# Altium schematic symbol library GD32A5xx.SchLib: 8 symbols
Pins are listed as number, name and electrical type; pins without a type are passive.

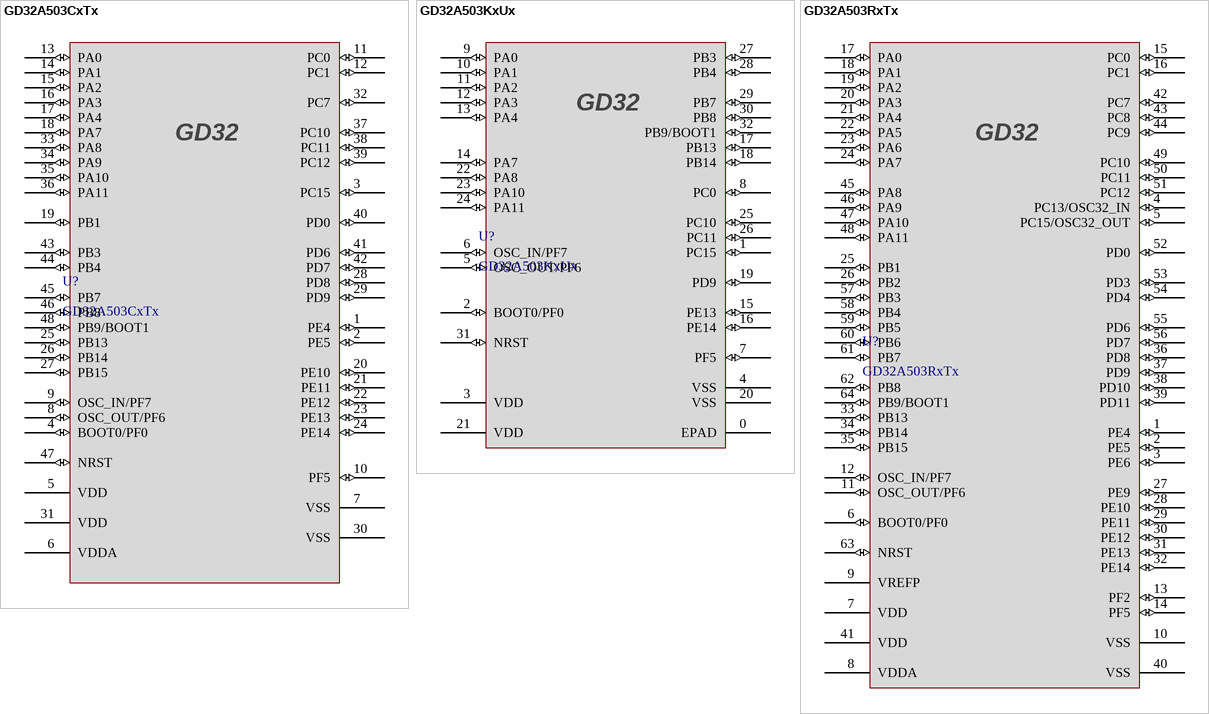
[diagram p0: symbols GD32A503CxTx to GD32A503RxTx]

## GD32A503CxTx
designator U?
footprint LQFP48_7x7x1.6
pins: 1 PE4 (io), 2 PE5 (io), 3 PC15 (io), 4 BOOT0/PF0 (io), 5 VDD (power), 6 VDDA (power), 7 VSS (power), 8 OSC_OUT/PF6 (io), 9 OSC_IN/PF7 (io), 10 PF5 (io), 11 PC0 (io), 12 PC1 (io), 13 PA0 (io), 14 PA1 (io), 15 PA2 (io), 16 PA3 (io), 17 PA4 (io), 18 PA7 (io), 19 PB1 (io), 20 PE10 (io), 21 PE11 (io), 22 PE12 (io), 23 PE13 (io), 24 PE14 (io), 25 PB13 (io), 26 PB14 (io), 27 PB15 (io), 28 PD8 (io), 29 PD9 (io), 30 VSS (power), 31 VDD (power), 32 PC7 (io), 33 PA8 (io), 34 PA9 (io), 35 PA10 (io), 36 PA11 (io), 37 PC10 (io), 38 PC11 (io), 39 PC12 (io), 40 PD0 (io), 41 PD6 (io), 42 PD7 (io), 43 PB3 (io), 44 PB4 (io), 45 PB7 (io), 46 PB8 (io), 47 NRST (io), 48 PB9/BOOT1 (io)

## GD32A503KxUx
designator U?
footprint QFN32_5X5X0.8
pins: 0 EPAD (power), 1 PC15 (io), 2 BOOT0/PF0 (io), 3 VDD (power), 4 VSS (power), 5 OSC_OUT/PF6 (io), 6 OSC_IN/PF7 (io), 7 PF5 (io), 8 PC0 (io), 9 PA0 (io), 10 PA1 (io), 11 PA2 (io), 12 PA3 (io), 13 PA4 (io), 14 PA7 (io), 15 PE13 (io), 16 PE14 (io), 17 PB13 (io), 18 PB14 (io), 19 PD9 (io), 20 VSS (power), 21 VDD (power), 22 PA8 (io), 23 PA10 (io), 24 PA11 (io), 25 PC10 (io), 26 PC11 (io), 27 PB3 (io), 28 PB4 (io), 29 PB7 (io), 30 PB8 (io), 31 NRST (io), 32 PB9/BOOT1 (io)

## GD32A503RxTx
designator U?
footprint LQPF64_10x10x1.6
pins: 1 PE4 (io), 2 PE5 (io), 3 PE6 (io), 4 PC13/OSC32_IN (io), 5 PC15/OSC32_OUT (io), 6 BOOT0/PF0 (io), 7 VDD (power), 8 VDDA (power), 9 VREFP (power), 10 VSS (power), 11 OSC_OUT/PF6 (io), 12 OSC_IN/PF7 (io), 13 PF2 (io), 14 PF5 (io), 15 PC0 (io), 16 PC1 (io), 17 PA0 (io), 18 PA1 (io), 19 PA2 (io), 20 PA3 (io), 21 PA4 (io), 22 PA5 (io), 23 PA6 (io), 24 PA7 (io), 25 PB1 (io), 26 PB2 (io), 27 PE9 (io), 28 PE10 (io), 29 PE11 (io), 30 PE12 (io), 31 PE13 (io), 32 PE14 (io), 33 PB13 (io), 34 PB14 (io), 35 PB15 (io), 36 PD8 (io), 37 PD9 (io), 38 PD10 (io), 39 PD11 (io), 40 VSS (power), 41 VDD (power), 42 PC7 (io), 43 PC8 (io), 44 PC9 (io), 45 PA8 (io), 46 PA9 (io), 47 PA10 (io), 48 PA11 (io), 49 PC10 (io), 50 PC11 (io), 51 PC12 (io), 52 PD0 (io), 53 PD3 (io), 54 PD4 (io), 55 PD6 (io), 56 PD7 (io), 57 PB3 (io), 58 PB4 (io), 59 PB5 (io), 60 PB6 (io), 61 PB7 (io), 62 PB8 (io), 63 NRST (io), 64 PB9/BOOT1 (io)

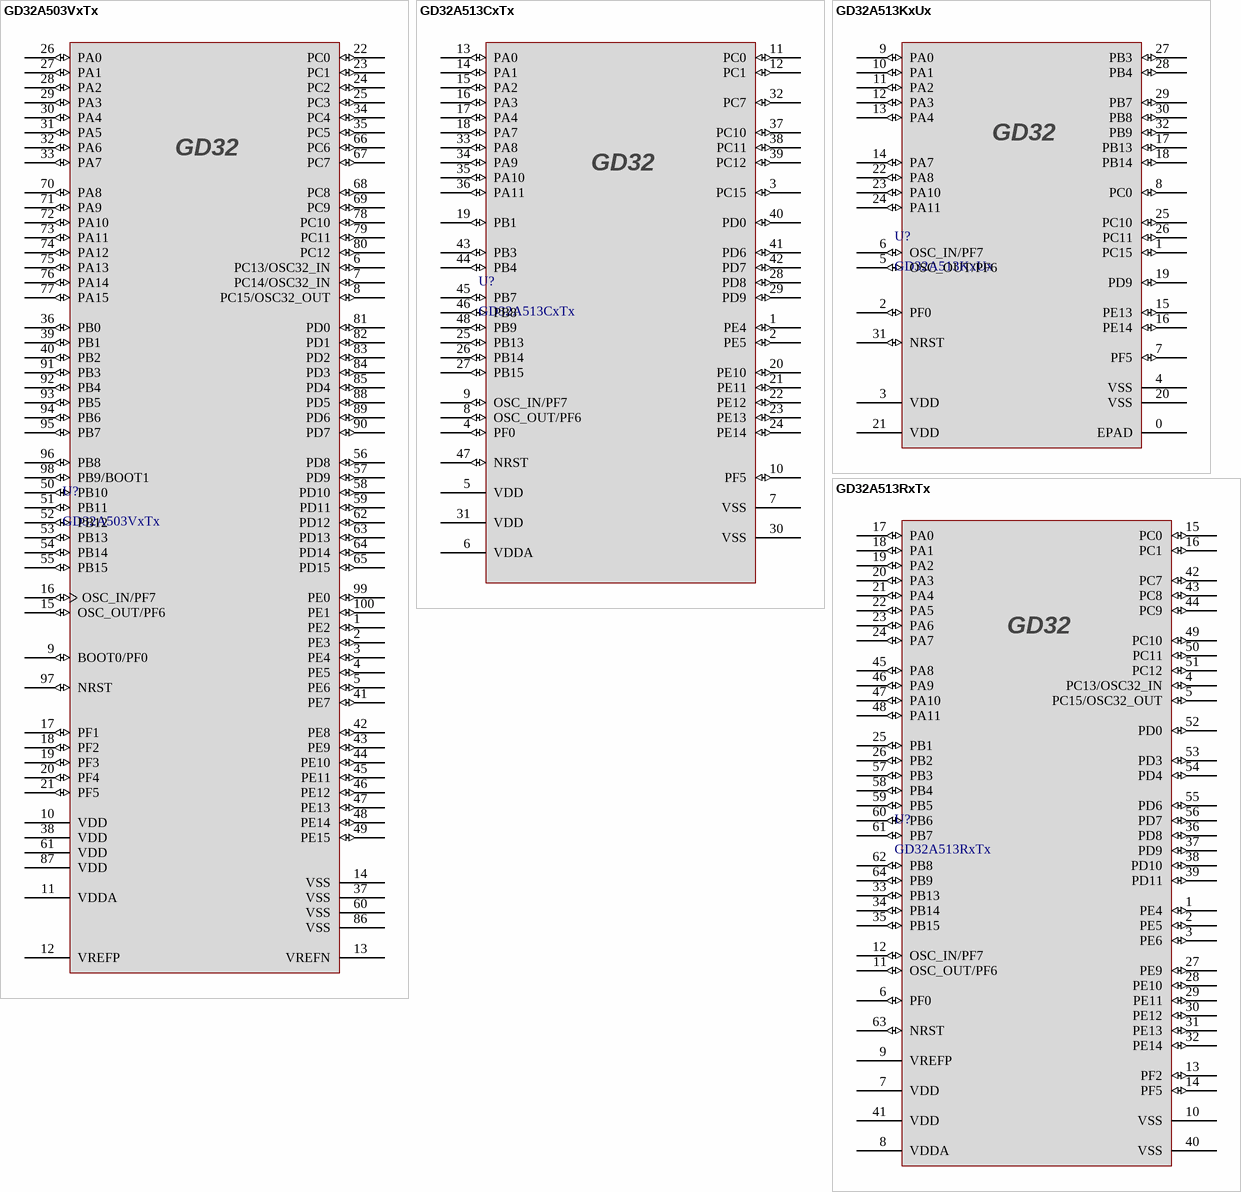
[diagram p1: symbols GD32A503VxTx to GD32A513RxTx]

## GD32A503VxTx
designator U?
footprint LQFP100_14x14x1.6
pins: 1 PE2 (io), 2 PE3 (io), 3 PE4 (io), 4 PE5 (io), 5 PE6 (io), 6 PC13/OSC32_IN (io), 7 PC14/OSC32_IN (io), 8 PC15/OSC32_OUT (io), 9 BOOT0/PF0 (io), 10 VDD (power), 11 VDDA (power), 12 VREFP (power), 13 VREFN (power), 14 VSS (power), 15 OSC_OUT/PF6 (io), 16 OSC_IN/PF7 (io), 17 PF1 (io), 18 PF2 (io), 19 PF3 (io), 20 PF4 (io), 21 PF5 (io), 22 PC0 (io), 23 PC1 (io), 24 PC2 (io), 25 PC3 (io), 26 PA0 (io), 27 PA1 (io), 28 PA2 (io), 29 PA3 (io), 30 PA4 (io), 31 PA5 (io), 32 PA6 (io), 33 PA7 (io), 34 PC4 (io), 35 PC5 (io), 36 PB0 (io), 37 VSS (power), 38 VDD (power), 39 PB1 (io), 40 PB2 (io), 41 PE7 (io), 42 PE8 (io), 43 PE9 (io), 44 PE10 (io), 45 PE11 (io), 46 PE12 (io), 47 PE13 (io), 48 PE14 (io), 49 PE15 (io), 50 PB10 (io), 51 PB11 (io), 52 PB12 (io), 53 PB13 (io), 54 PB14 (io), 55 PB15 (io), 56 PD8 (io), 57 PD9 (io), 58 PD10 (io), 59 PD11 (io), 60 VSS (power), 61 VDD (power), 62 PD12 (io), 63 PD13 (io), 64 PD14 (io), 65 PD15 (io), 66 PC6 (io), 67 PC7 (io), 68 PC8 (io), 69 PC9 (io), 70 PA8 (io), 71 PA9 (io), 72 PA10 (io), 73 PA11 (io), 74 PA12 (io), 75 PA13 (io), 76 PA14 (io), 77 PA15 (io), 78 PC10 (io), 79 PC11 (io), 80 PC12 (io), 81 PD0 (io), 82 PD1 (io), 83 PD2 (io), 84 PD3 (io), 85 PD4 (io), 86 VSS (power), 87 VDD (power), 88 PD5 (io), 89 PD6 (io), 90 PD7 (io), 91 PB3 (io), 92 PB4 (io), 93 PB5 (io), 94 PB6 (io), 95 PB7 (io), 96 PB8 (io), 97 NRST (io), 98 PB9/BOOT1 (io), 99 PE0 (io), 100 PE1 (io)

## GD32A513CxTx
designator U?
footprint LQFP48_7x7x1.6
pins: 1 PE4 (io), 2 PE5 (io), 3 PC15 (io), 4 PF0 (io), 5 VDD (power), 6 VDDA (power), 7 VSS (power), 8 OSC_OUT/PF6 (io), 9 OSC_IN/PF7 (io), 10 PF5 (io), 11 PC0 (io), 12 PC1 (io), 13 PA0 (io), 14 PA1 (io), 15 PA2 (io), 16 PA3 (io), 17 PA4 (io), 18 PA7 (io), 19 PB1 (io), 20 PE10 (io), 21 PE11 (io), 22 PE12 (io), 23 PE13 (io), 24 PE14 (io), 25 PB13 (io), 26 PB14 (io), 27 PB15 (io), 28 PD8 (io), 29 PD9 (io), 30 VSS (power), 31 VDD (power), 32 PC7 (io), 33 PA8 (io), 34 PA9 (io), 35 PA10 (io), 36 PA11 (io), 37 PC10 (io), 38 PC11 (io), 39 PC12 (io), 40 PD0 (io), 41 PD6 (io), 42 PD7 (io), 43 PB3 (io), 44 PB4 (io), 45 PB7 (io), 46 PB8 (io), 47 NRST (io), 48 PB9 (io)

## GD32A513KxUx
designator U?
footprint QFN32_5X5X0.8
pins: 0 EPAD (power), 1 PC15 (io), 2 PF0 (io), 3 VDD (power), 4 VSS (power), 5 OSC_OUT/PF6 (io), 6 OSC_IN/PF7 (io), 7 PF5 (io), 8 PC0 (io), 9 PA0 (io), 10 PA1 (io), 11 PA2 (io), 12 PA3 (io), 13 PA4 (io), 14 PA7 (io), 15 PE13 (io), 16 PE14 (io), 17 PB13 (io), 18 PB14 (io), 19 PD9 (io), 20 VSS (power), 21 VDD (power), 22 PA8 (io), 23 PA10 (io), 24 PA11 (io), 25 PC10 (io), 26 PC11 (io), 27 PB3 (io), 28 PB4 (io), 29 PB7 (io), 30 PB8 (io), 31 NRST (io), 32 PB9 (io)

## GD32A513RxTx
designator U?
footprint LQPF64_10x10x1.6
pins: 1 PE4 (io), 2 PE5 (io), 3 PE6 (io), 4 PC13/OSC32_IN (io), 5 PC15/OSC32_OUT (io), 6 PF0 (io), 7 VDD (power), 8 VDDA (power), 9 VREFP (power), 10 VSS (power), 11 OSC_OUT/PF6 (io), 12 OSC_IN/PF7 (io), 13 PF2 (io), 14 PF5 (io), 15 PC0 (io), 16 PC1 (io), 17 PA0 (io), 18 PA1 (io), 19 PA2 (io), 20 PA3 (io), 21 PA4 (io), 22 PA5 (io), 23 PA6 (io), 24 PA7 (io), 25 PB1 (io), 26 PB2 (io), 27 PE9 (io), 28 PE10 (io), 29 PE11 (io), 30 PE12 (io), 31 PE13 (io), 32 PE14 (io), 33 PB13 (io), 34 PB14 (io), 35 PB15 (io), 36 PD8 (io), 37 PD9 (io), 38 PD10 (io), 39 PD11 (io), 40 VSS (power), 41 VDD (power), 42 PC7 (io), 43 PC8 (io), 44 PC9 (io), 45 PA8 (io), 46 PA9 (io), 47 PA10 (io), 48 PA11 (io), 49 PC10 (io), 50 PC11 (io), 51 PC12 (io), 52 PD0 (io), 53 PD3 (io), 54 PD4 (io), 55 PD6 (io), 56 PD7 (io), 57 PB3 (io), 58 PB4 (io), 59 PB5 (io), 60 PB6 (io), 61 PB7 (io), 62 PB8 (io), 63 NRST (io), 64 PB9 (io)

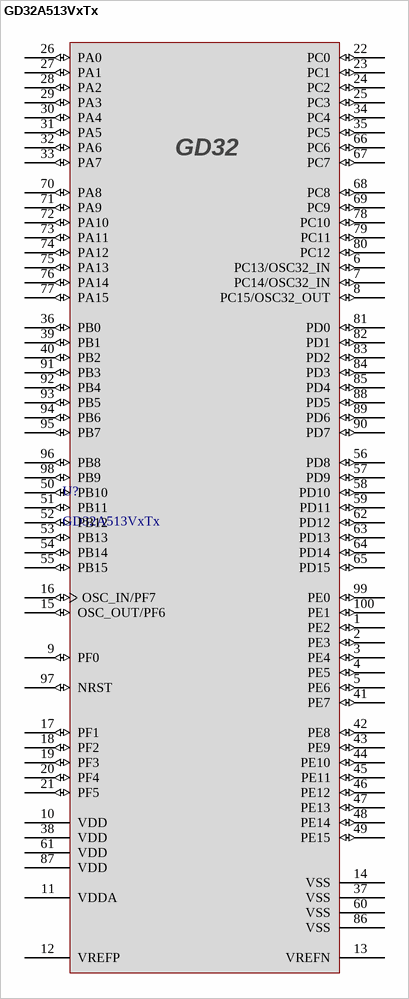
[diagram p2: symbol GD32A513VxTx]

## GD32A513VxTx
designator U?
footprint LQFP100_14x14x1.6
pins: 1 PE2 (io), 2 PE3 (io), 3 PE4 (io), 4 PE5 (io), 5 PE6 (io), 6 PC13/OSC32_IN (io), 7 PC14/OSC32_IN (io), 8 PC15/OSC32_OUT (io), 9 PF0 (io), 10 VDD (power), 11 VDDA (power), 12 VREFP (power), 13 VREFN (power), 14 VSS (power), 15 OSC_OUT/PF6 (io), 16 OSC_IN/PF7 (io), 17 PF1 (io), 18 PF2 (io), 19 PF3 (io), 20 PF4 (io), 21 PF5 (io), 22 PC0 (io), 23 PC1 (io), 24 PC2 (io), 25 PC3 (io), 26 PA0 (io), 27 PA1 (io), 28 PA2 (io), 29 PA3 (io), 30 PA4 (io), 31 PA5 (io), 32 PA6 (io), 33 PA7 (io), 34 PC4 (io), 35 PC5 (io), 36 PB0 (io), 37 VSS (power), 38 VDD (power), 39 PB1 (io), 40 PB2 (io), 41 PE7 (io), 42 PE8 (io), 43 PE9 (io), 44 PE10 (io), 45 PE11 (io), 46 PE12 (io), 47 PE13 (io), 48 PE14 (io), 49 PE15 (io), 50 PB10 (io), 51 PB11 (io), 52 PB12 (io), 53 PB13 (io), 54 PB14 (io), 55 PB15 (io), 56 PD8 (io), 57 PD9 (io), 58 PD10 (io), 59 PD11 (io), 60 VSS (power), 61 VDD (power), 62 PD12 (io), 63 PD13 (io), 64 PD14 (io), 65 PD15 (io), 66 PC6 (io), 67 PC7 (io), 68 PC8 (io), 69 PC9 (io), 70 PA8 (io), 71 PA9 (io), 72 PA10 (io), 73 PA11 (io), 74 PA12 (io), 75 PA13 (io), 76 PA14 (io), 77 PA15 (io), 78 PC10 (io), 79 PC11 (io), 80 PC12 (io), 81 PD0 (io), 82 PD1 (io), 83 PD2 (io), 84 PD3 (io), 85 PD4 (io), 86 VSS (power), 87 VDD (power), 88 PD5 (io), 89 PD6 (io), 90 PD7 (io), 91 PB3 (io), 92 PB4 (io), 93 PB5 (io), 94 PB6 (io), 95 PB7 (io), 96 PB8 (io), 97 NRST (io), 98 PB9 (io), 99 PE0 (io), 100 PE1 (io)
